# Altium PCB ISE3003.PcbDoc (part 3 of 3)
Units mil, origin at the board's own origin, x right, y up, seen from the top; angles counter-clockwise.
Board outline 3937.01 x 3937.01 mil, 2 copper layers (Top Layer, Bottom Layer), stack 62 mil thick; 230 components, 119 nets, 522 pads, 174 vias.
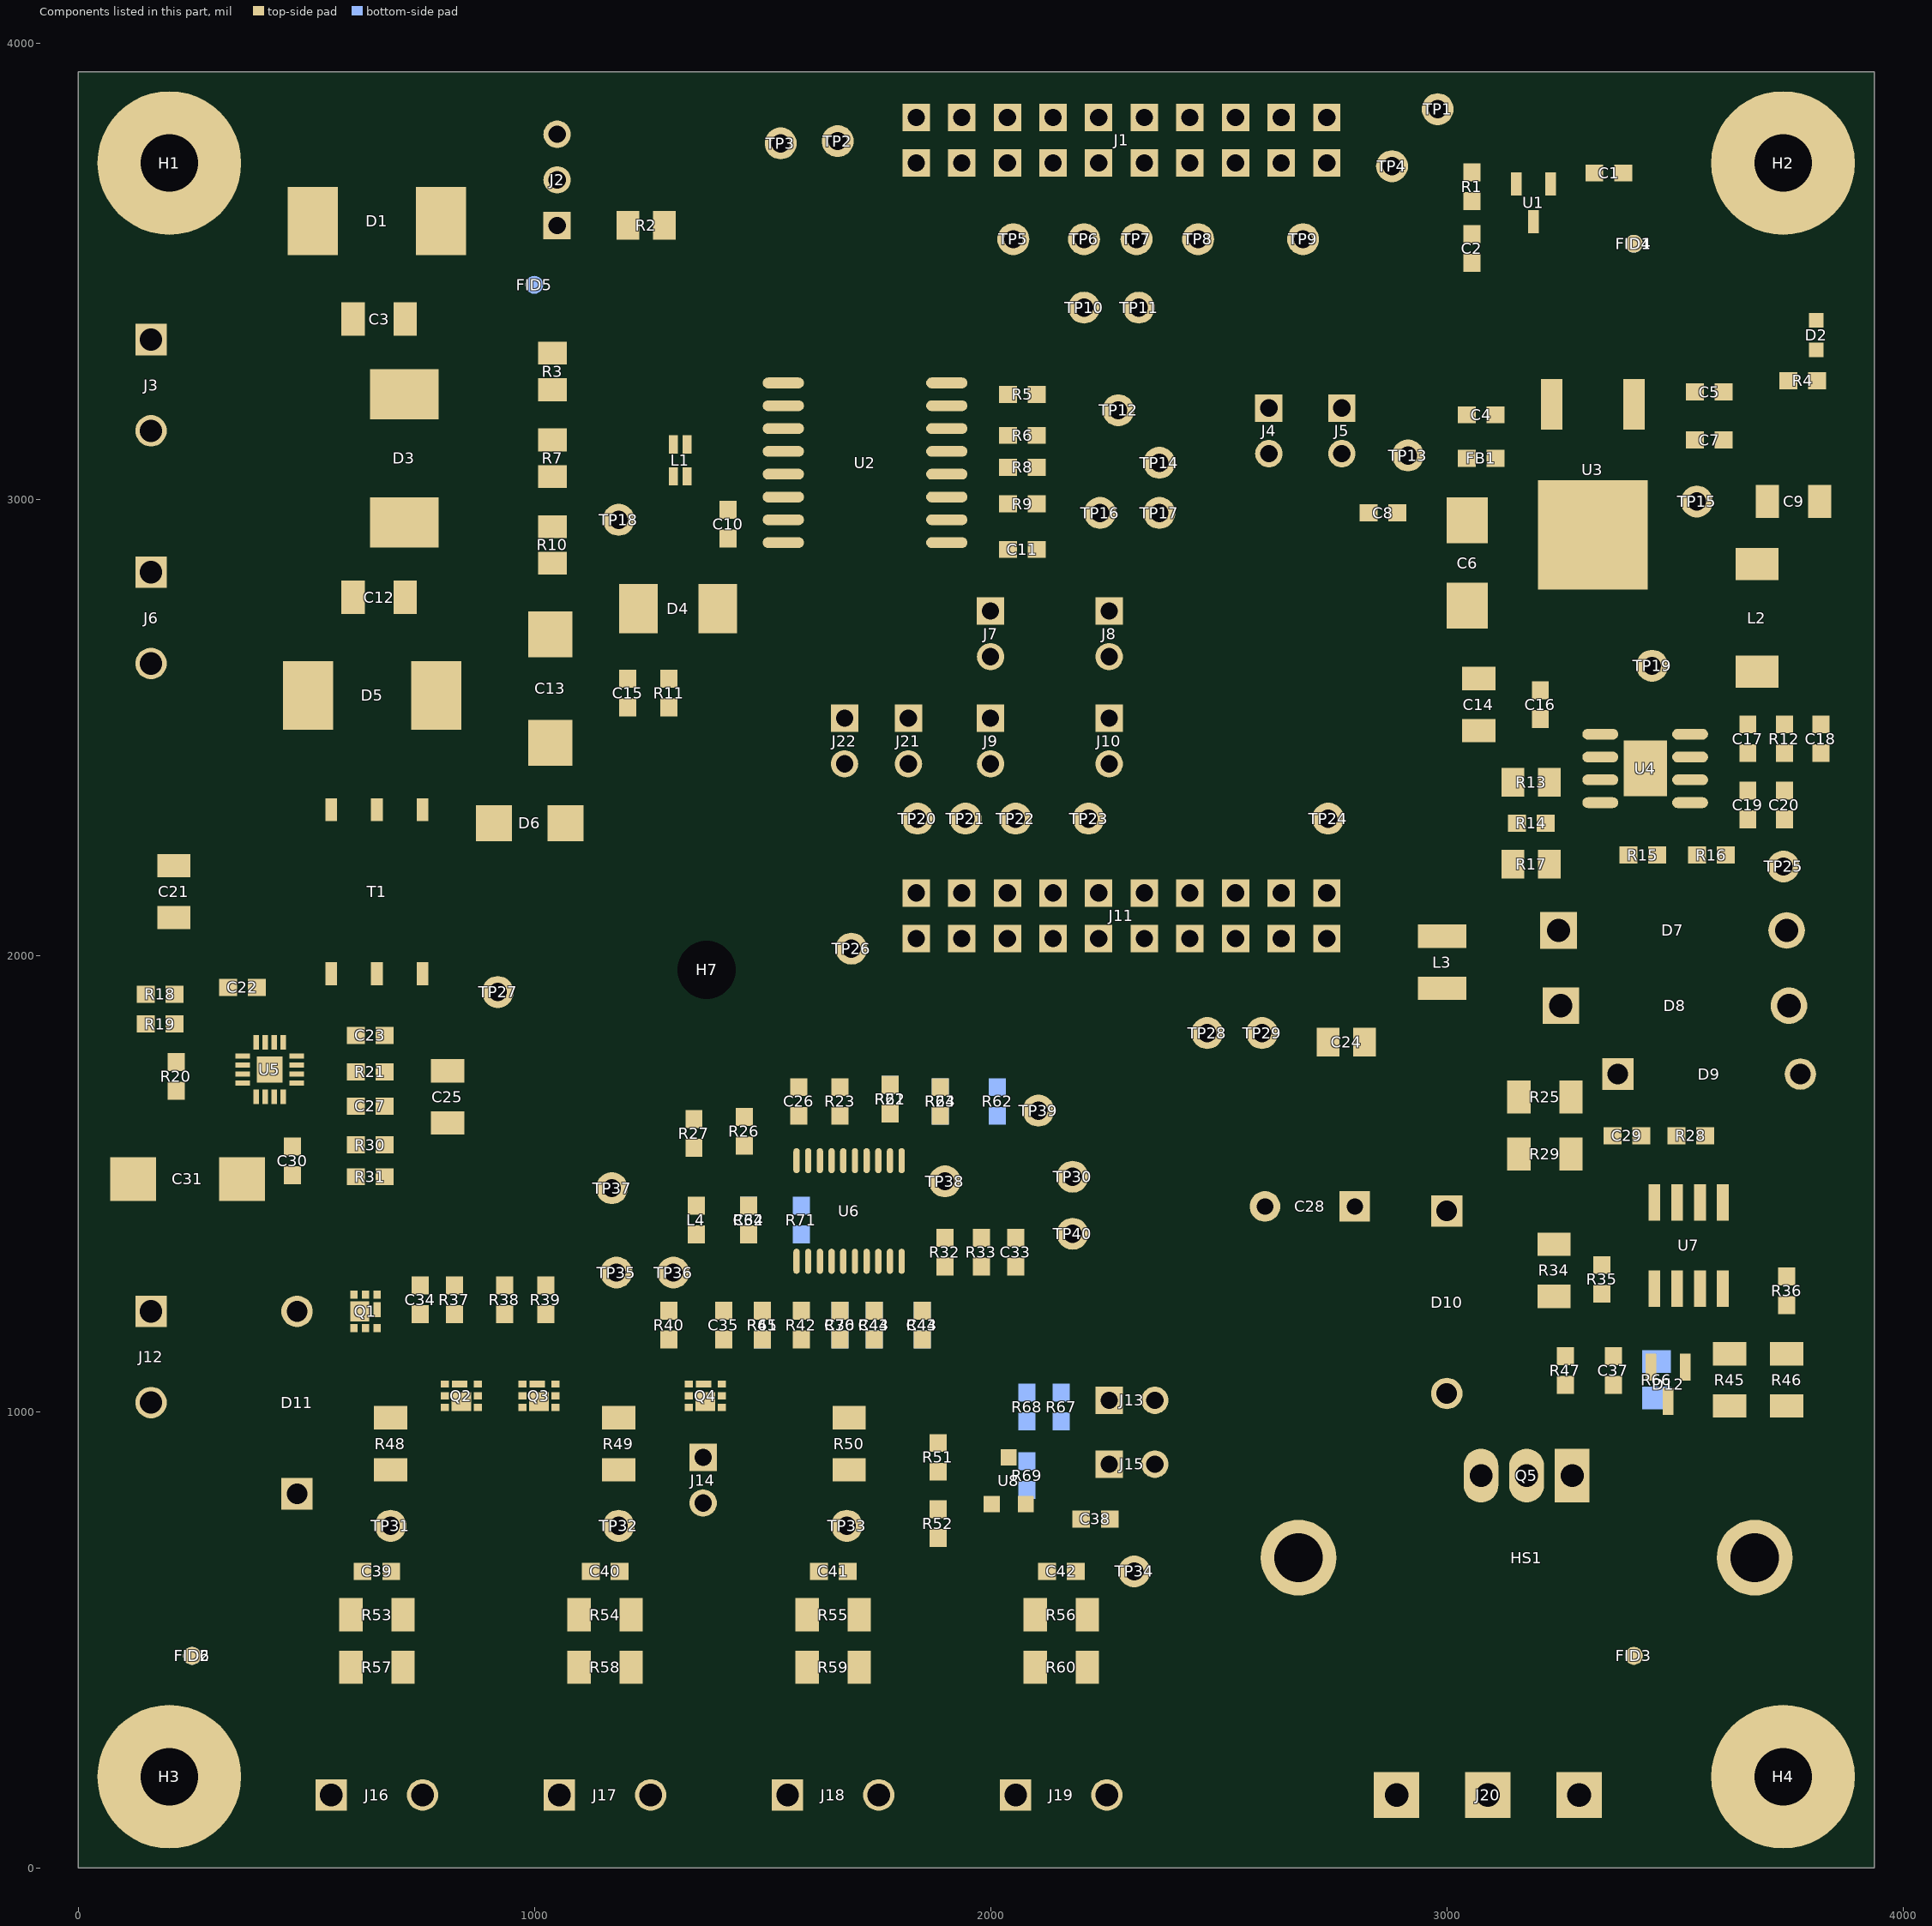
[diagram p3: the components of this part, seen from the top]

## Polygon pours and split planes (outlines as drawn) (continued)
NetQ4_1 on Top Layer "Top Layer-No Net 1" (hatched 90Degree grid 5 track 8, remove dead copper, pour order 52): 1305,1025 1310,1030 1475,1030 1485,1020 1730,1020 1740,1010 1740,965 1725,950 1465,950 1440,975 1310,975 1305,980
NetQ3_1 on Top Layer "Top Layer-No Net 1" (hatched 90Degree grid 5 track 8, remove dead copper, pour order 53): 960,955 950,965 950,1025 955,1030 1245,1030 1250,1025 1250,966.43 1240.62,955
NetC22_1 on Top Layer "Bottom Layer-No Net" (hatched 90Degree grid 5 track 8, remove dead copper, pour order 77): 425,1805 429.85,1809.55 430,1820 425,1820 425,1845 430,1850 444.95,1864.85 549.95,1864.85 568,1882.9 568,1927.95 559.95,1934.85 560,1970 560,1975 385,1975 375,1965 375,1890 360,1875 360,1810 365,1805
NetQ2_1 on Top Layer "Top Layer-No Net 1" (hatched 90Degree grid 5 track 8, remove dead copper, pour order 56): 890.18,960 900,970 900,1020 890.18,1030 762.46,1030 752.63,1020 629.82,1020 620,1010 620,970 629.82,960
NetC25_1 on Top Layer "Bottom Layer-No Net" (hatched 90Degree grid 5 track 8, remove dead copper, pour order 79): 774.57,1725 775,1830 775,1895 745,1925 745,1985 980,1985 990,1975 990,1755 960,1725
GND on Top Layer "Bottom Layer-No Net" (hatched 90Degree grid 5 track 8, remove dead copper, pour order 70): 3465,1015 3815,1015 3845,985 3845,890 3795,840 3790,840 3510,840 3500,850 3460,890 3460,945 3460,1010 3465,1015
NetC17_2 on Top Layer "Bottom Layer-No Net" (hatched 90Degree grid 5 track 8, remove dead copper, pour order 68): 3765,2485 3775,2495 3775,2660 3760,2675 3430,2675 3420,2665 3420,2610 3510,2520 3510,2485
NetC37_1 on Top Layer "Bottom Layer-No Net" (hatched 90Degree grid 5 track 8, remove dead copper, pour order 63): 3205,1100 3165,1140 3165,1255 3180,1270 3380,1270 3405,1295 3450,1295 3460,1285 3460,1200 3415,1155 3415,1110 3405,1100
NetC37_2 on Top Layer "Bottom Layer-No Net" (hatched 90Degree grid 5 track 8, remove dead copper, pour order 46): 3410,735 3435,760 3435,955 3405,985 3405,1060 3395,1070 3255,1070 3245,1060 3245,755 3265,735
NetC14_2 on Top Layer "Bottom Layer-No Net" (hatched 90Degree grid 5 track 8, remove dead copper, pour order 67): 3045,2025 3035,2015 2875,2015 2860,2035 2860,2500 2880,2520 3255,2520 3265,2510 3265,2445 3255,2435 3170,2435 3160,2425 3160,2360 3155,2355 3080,2355 3060,2335 3060,2260 3075,2245 3160,2245 3165,2240 3165,2175 3150,2160 3080,2160 3045,2125
16V_C on Top Layer "Bottom Layer-No Net" (hatched 90Degree grid 5 track 8, remove dead copper, pour order 64): 3180,1340 3285,1340 3310,1365 3310,1420 3315,1425 3460,1425 3460,1495 3385,1570 3385,1655 3415,1685 3415,1890 3375,1930 3215,1930 3205,1920 3205,1800 3245,1760 3245,1505 3165,1425 3165,1355
39V on Top Layer "Bottom Layer-No Net" (hatched 90Degree grid 5 track 8, remove dead copper, pour order 66): 2900,1410 3120,1410 3120,1465 3190,1535 3190,1720 3155,1755 3155,1935 3190,1970 3310,1970 3320,1980 3320,2100 3305,2115 3110,2115 3095,2100 3095,1985 3075,1965 2870,1965 2850,1945 2850,1910 2800,1860 2800,1750 2750,1700 2750,1390 2770,1370 2860,1370
EGND on Top Layer "Top Layer-No Net" (hatched 90Degree grid 5 track 8, remove dead copper, pour order 58): 415,3515 385,3485 385,3325 405,3305 585,3305 625,3345 625,3790 605,3810 440,3810 415,3785
NetD6_2 on Top Layer "Top Layer-No Net" (hatched 90Degree grid 5 track 8, remove dead copper, pour order 60): 750,2300 735,2315 735,2375 750,2390 890,2390 950,2330 950,2240 945,2235 870,2235 865,2240 865,2285 850,2300
C5V on Top Layer "Bottom Layer-No Net" (hatched 90Degree grid 5 track 8, remove dead copper, pour order 72): 1140,2250 1155,2270 1155,2345 1230,2420 1325,2420 1335,2430 1335,2540 1325,2550 1180,2550 1140,2510 1035,2510 1020,2495 1020,2485 1015,2480 1015,2265 1030,2250
PGND on Top Layer "Bottom Layer-No Net" (hatched 90Degree grid 5 track 8, remove dead copper, pour order 62): 925,2590 885,2630 885,2775 910,2800 1080,2800 1150,2870 1250,2870 1260,2860 1260,2600 1250,2590
PGND on Top Layer "Bottom Layer-No Net" (hatched 90Degree grid 5 track 8, remove dead copper, pour order 78): 290,2185 130,2185 110,2205 110,2340 115,2345 120,2350 235,2350 295,2350 305,2340 305,2310 305,2195 295,2185 290,2185
GND on Top Layer "Bottom Layer-No Net" (hatched 90Degree grid 5 track 8, remove dead copper, pour order 76): 85,2095 330,2095 345,2080 345,2050 345,2045 330,2030 320,2020 205,2020 90,2020 75,2035 75,2075 75,2085 85,2095
NetD10_2 on Top Layer "Bottom Layer-No Net" (hatched 90Degree grid 5 track 8, remove dead copper, pour order 51): 3135,1130 3150,1115 3150,1020 3210,960 3210,715 3275,650 3275,425 3380,320 3380,90 3350,60 3210,60 3190,80 3190,295 3140,345 3140,930 3090,980 2945,980 2925,1000 2925,1105 2950,1130
GND on Top Layer "Bottom Layer-No Net" (hatched 90Degree grid 5 track 8, remove dead copper, pour order 59): 3140,55 3025,55 3000,80 3000,920 3005,925 3100,925 3110,915 3110,805 3085,780 3085,275 3145,215 3145,60
EGND on Top Layer "Top Layer-No Net" (hatched 90Degree grid 5 track 8, remove dead copper, pour order 48): 400,2445 390,2455 390,2785 465,2860 610,2860 625,2845 625,2730 570,2675 570,2455 560,2445
12V on Top Layer "Top Layer-No Net" (hatched 90Degree grid 5 track 8, remove dead copper, pour order 43): 3730,2810 3534.33,2810 3505,2840 3505,3095 3497,3102.95 3472,3127.95 3367,3127.95 3345,3150 3345,3330 3365,3350 3550,3350 3560,3340 3560,3085 3570,3075 3740,3075 3750,3065 3750,2830
GND on Top Layer "Bottom Layer-No Net" (hatched 90Degree grid 5 track 8, remove dead copper, pour order 71): 3645,1350 3610,1385 3610,1580 3640,1610 3675,1610 3690,1625 3690,1675 3650,1715 3500,1715 3475,1740 3475,1915 3366,2024 3366,2117 3326,2157 3326,2252 3395,2321 3395,2463 3388,2470 3316,2470 3300,2486 3300,2548 3283,2565 2865,2565 2805,2505 2805,2235 2775,2205 1815,2205 1740,2130 1740,2070 1735,2065 1560,2065 1525,2100 1525,2310 1970,2755 2090,2755 2145,2810 2145,2935 2150,2940 2190,2940 2230,2900 2340,2900 2350,2910 2350,3230 2325,3255 2278,3255 2258,3275 2258,3305 2283,3330 2835,3330 2850,3315 2850,2845 2885,2810 3145,2810 3185,2850 3185,3020 3210,3045 3450,3045 3450,2790 3360,2700 3360,2605 3475,2490 3475,2327 3410,2262 3410,2160 3610,1960 3780,1960 3820,1920 3820,1370 3800,1350
NetC4_1 on Top Layer "Top Layer-No Net" (hatched 90Degree grid 5 track 8, remove dead copper, pour order 55): 3095,3085 3105,3075 3265,3075 3265,3255 3245,3275 3120,3275 3095,3250
UC3.3V on Top Layer "Top Layer-No Net" (hatched 90Degree grid 5 track 8, remove dead copper, pour order 47): 2990,2900 2965,2875 2890,2875 2880,2885 2880,3150 2895,3165 2970,3165 3000,3135 3050,3135 3055,3130 3055,3010 3065,3000 3135,3000 3145,2990 3145,2905 3140,2900
GND on Top Layer "Top Layer-No Net 1" (hatched 90Degree grid 5 track 8, remove dead copper, pour order 45): 2615,1765 2635,1745 2635,1340 2690,1285 2690,1160 2650,1120 2395,1120 2375,1140 2375,1720 2420,1765
GND on Top Layer "Bottom Layer-No Net" (hatched 90Degree grid 5 track 8, remove dead copper, pour order 69): 3800,3210 3800,3070 3815,3055 3815,2770 3820,2765 3895,2765 3900,2770 3900,3510 3885,3525 3550,3525 3505,3480 3505,3395 3515,3385 3600,3385 3615,3400 3770,3400 3795,3375 3840,3375 3850,3365 3850,3230 3840,3220 3810,3220
VREF_PH on Bottom Layer "Top Layer-No Net 1" (hatched 90Degree grid 5 track 8, remove dead copper, pour order 82): 1280,1130 1330,1180 1385,1180 1400,1165 1400,1047 1364,1011 739,1011 705,1045 705,1115 720,1130
EGND on Bottom Layer "Bottom Layer-No Net" (hatched 90Degree grid 5 track 8, remove dead copper, pour order 57): 475,2835 560,2835 580,2815 580,2521 505,2446 60,2446 35,2471 35,3425 85,3475 500,3475 550,3425 550,3235 520,3205 333,3205 305,3233 305,3385 264,3426 85,3426 70,3411 70,2705 85,2690 415,2690 445,2720 445,2805
PGND on Bottom Layer "Bottom Layer-No Net" (hatched 90Degree grid 5 track 8, remove dead copper, pour order 81): 475,2295 965,2295 1305,2630 1305,2860 1335,2890 1410,2890 1500,2980 1500,3275 1400,3375 685,3375 645,3335 645,2965 630,2950 150,2950 125,2925 125,2780 140,2765 190,2765 310,2885 650,2885 650,2430 620,2400 485,2400 435,2350 150,2350 100,2300 100,2215 130,2185 365,2185
GND on Bottom Layer "Top Layer-No Net 1" (hatched 90Degree grid 5 track 8, remove dead copper, pour order 50): 598,1335 678,1335 723,1290 723,1223 655,1155 655,1040 655,988 693,950 693,885 678,870 581,870 575,876 575,921 575,1327 583,1335
12V on Bottom Layer "Bottom Layer-No Net" (hatched 90Degree grid 5 track 8, remove dead copper, pour order 65): 3755,2760 3715,2800 3550,2800 3505,2845 3505,3015 3545,3056 3840,3056 3865,3031 3865,440 3840,415 3520,415 3375,270 440,270 325,385 325,785 305,805 140,805 100,845 100,1035 120,1055 510,1055 530,1035 530,790 415,675 415,436 506,345 2679,345 2979,645 3600,645 3660,705 3660,1060 3630,1090 3630,1620 3620,1630 3520,1630 3510,1640 3510,1675 3550,1715 3550,2135 3755,2340
GND on Bottom Layer "Bottom Layer-No Net" (hatched 90Degree grid 5 track 8, remove dead copper, pour order 61): 3850,3900 3900,3850 3900,3165 3835,3100 3480,3100 3465,3085 3465,2710 3485,2690 3665,2690 3683,2670 3713,2640 3715,2345 3520,2150 3520,1770 3600,1690 3600,815 3465,680 2920,680 2650,410 590,410 460,540 460,680 575,795 575,925 615,965 1405,965 1430,990 1430,1185 1335,1280 1305,1280 1295,1270 1295,1195 1275,1175 665,1175 560,1280 110,1280 50,1340 50,2080 80,2110 350,2110 470,1990 470,1860 500,1830 969,1830 1020,1881 1020,1970 1040,1990 1210,1990 1990,2770 1990,3240 1950,3280 1950,3540 1780,3710 1780,3880 1800,3900

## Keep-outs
Keep-Out Layer:
  lines w10: -5,3969.53 -5,-5 3970.75,-5 3970.75,3969.52 ; 0,3969.53 3969.53,3969.53
  text ".Layer_Name" at 577,-858.49 h60

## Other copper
Top Layer:
  pour cut-out: 2390.95,2915 2425,2949.05 2425,3113 2393,3145 2305,3145 2280,3120 2280,2915
  pour cut-out: 1925,2723 1983,2665 2055,2665 2055,2790 2045,2800 1935,2800 1925,2790
  pour cut-out: 2716,3050 2729,3037 2804,3037 2823,3056 2823,3240 2809,3254 2726,3254 2716,3244
  pour cut-out: 2561,3055 2574,3042 2649,3042 2668,3061 2668,3245 2654,3259 2571,3259 2561,3249
  pour cut-out: 1786.15,2322.48 1823.67,2360 2083,2360 2115,2328 2115,2255 1786.15,2255
  pour cut-out: 1880,2260 1880,2563 1823,2620 1700,2620 1645,2565 1645,2260
  text ".Layer_Name" at 577,-858.49 h60
Bottom Layer:
  pour cut-out: 2418,3522 2516,3522 2516,3578 2514,3580 2428,3580 2415,3567 2415,3525 2417,3523 2418,3523
  pour cut-out: 3618,1627 3610,1635 3575,1635 3566.5,1626.5 3566.5,1443 3618,1443
  pour cut-out: 3432.5,1333.5 3545,1221 3545,1180 3448,1180 3325,1303 3325,1333.5
  pour cut-out: 3405,1231 3403,1229 3403,980 3523,980 3563,1020 3563,1183 3541,1205 3458,1205 3433,1230 3406,1230
  pour cut-out: 3550,1685 3550,1755 3555,1760 3610,1705 3610,1686 3581,1686 3575,1680 3555,1680
  pour cut-out: 3040,3930 3040,3790 3025,3775 2905,3775 2875,3805 2875,3920 2885,3930
  pour cut-out: 2755,3075 2800,3030 2810,3030 2855,3075 2855,3245 2820,3280 2794,3280 2753,3239 2753,3080
  pour cut-out: 2897.29,3705 2937.29,3665 2960,3665 2965,3670 2965,3770 3018,3823 3018,3907 2995,3930 2775,3930 2725,3880 2725,3735 2755,3705
  pour cut-out: 2695,3675 2778,3675 2810,3707 2810,3786 2800,3796 2736,3796 2715,3775 2695,3775
  pour cut-out: 2659,3416 2635,3440 2540,3440 2535,3435 2535,3375 2549,3361 2586,3361 2586,3274 2561,3249 2561,3132 2561.01,3101 2561.16,3096 2561.83,3091 2660.14,3090
  pour cut-out: 2170,3350 2175,3345 2219,3345 2251.92,3377.92 2290.08,3377.92 2303,3365 2357.87,3365 2410,3417.13 2410,3430 2390,3450 2180,3450 2170,3440
  pour cut-out: 2125,3115 2180,3115 2180,3090 2125,3090
  pour cut-out: 2371,3391 2245.73,3391 2125,3511.73 2125,3640 2150,3665 2405,3665 2435,3635 2435,3455
  pour cut-out: 2385,3050 2385,3100 2285,3200 2200,3200 2200,3060 2225,3035 2370,3035
  pour cut-out: 2405,2921 2219,2921 2200,2940 2200,3060 2385,3060 2385,2940 2395,2930 2405,2930
  pour cut-out: 1915,2200 1885,2230 1885,2745 1949.5,2809.5 2291.5,2809.5 2323,2778 2323,2213 2310,2200
  pour cut-out: 1715,1415 1715,1385 1690,1360 1690,1355 1655,1355 1645,1365 1645,1410 1650,1415
  pour cut-out: 1535,1600 1535,1675 1650,1790 1885,1790 1885,1695 1919.89,1695 1933,1681.89 1933,1600
  pour cut-out: 1495,1645 1495,1700 1505,1710 1510,1705 1550,1705 1550,1695 1560,1685 1555,1680 1555,1650 1535,1650 1530,1645
  pour cut-out: 1663,1614.82 1662.82,1615 1595,1615 1595,1690 1610,1705 1665,1705 1680,1690 1680,1616.82 1678,1614.82
  pour cut-out: 1808,1614.82 1660.18,1614.82 1645,1630 1645,1730 1690,1775 1880,1775 1898,1757 1898,1633 1880,1615 1808.18,1615
  pour cut-out: 1959.82,1260.18 1965,1255 1965,1190 1957.81,1182.81 1710.19,1182.81 1698,1195 1698,1250.88 1707.3,1260.18
  pour cut-out: 2170,1075 2170,1085 2378,1085 2413,1050 2413,975 2393,955 2180,955 2160,975 2160,1065
  pour cut-out: 3065,1335 3065,1525 2920,1525 2920,1366 2951,1335
  pour cut-out: 1480,670 1480,705 1475,710 1445,680 1445,670 1455,670 1460,665 1475,665
  pour cut-out: 1600,740 1715,740 1715,720 1735,700 1755,700 1765,710 1765,765 1785,785 1785,845 1755,875 1700,875 1670,905 1660,905 1525,770 1525,750 1525.23,750 1545.23,730 1595,730 1600,735
  pour cut-out: 1315,1250 1305,1255 1303,1278 1398,1370 1480,1370 1480,1305 1475,1300 1385,1300 1335,1250
  pour cut-out: 1580,918 1580,910 1550,880 1490,880 1475,895 1475,947 1493,965 1533,965
  pour cut-out: 1321,769 1325,765 1410,765 1530,885 1530,970.77 1509.77,991 1345,991 1321,967
  pour cut-out: 1410,770 1394,786 1201,786 1185,770 1185,705 1195,695 1405,695 1410,700
  pour cut-out: 1530,1205 1537.7,1212.7 1537.7,1307.3 1530,1315 1465,1315 1462.3,1312.3 1462.3,1206 1463.3,1205
  pour cut-out: 2228,836 2180.24,836 2099.24,755 2041,755 2041,1101 2063,1123 2136,1123 2148,1111 2148,928 2163,913 2228,913
  pour cut-out: 2785,2191 2800,2176 2800,2016 2764,1980 1798,1980 1770,2008 1770,2171 1790,2191
  pour cut-out: 2785,3891 2800,3876 2800,3716 2764,3680 1798,3680 1770,3708 1770,3871 1790,3891
  pour cut-out: 1420,2870 1335,2870 1325,2880 1325,2942 1338,2955 1413,2955 1420,2948 1420,2895 1425,2890 1425,2875
  pour cut-out: 1455,2880 1410,2925 1400,2925 1396.46,2921.46 1396.46,2868.54 1405,2860 1450,2860 1455,2865
  pour cut-out: 3328,773 3343,788 3343,938 3333,948 3152,948 3118.87,914.87 3118.87,784.13 3130,773
  pour cut-out: 1605.06,1875 1605.06,1970 1635.06,2000 1650,2000 1690,1960 1690,1900 1665,1875
  pour cut-out: 1575,2380 1620,2335 1670,2335 1690,2355 1690,2445 1670,2465 1590,2465 1575,2450
  pour cut-out: 2126,1607 2024,1607 2024,1681 2044,1701 2150,1701 2153.78,1697.22 2153.78,1634.78
  pour cut-out: 1344,1461 1306,1499 1281,1474 1216,1474 1158,1416 1158,1345 1175,1345 1209,1311 1265,1367 1265,1375 1333,1375 1344,1386
  pour cut-out: 1225,1630 1175,1630 1165,1640 1210,1685 1260,1685 1270,1675 1260,1665 1260,1655 1250,1655
  text ".Layer_Name" at 577,-858.49 h60

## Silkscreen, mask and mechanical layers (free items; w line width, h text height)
Top Overlay:
  circle w15: c1380,3050 r6
  circle w8: c751,1861 r38
  circle w8: c1066,1918 r38
  lines w6: 480.57,1658 328,1658 328,1842 512,1842 512,1690 ; 712,1820 712,1866 566,1866 566,1464 714,1464 714,1600 ; 713,1669 713,1755 ; 1255,1380 1275,1360 ; 1903,2420 1903,2349 1916,2336 ; 2025,1110 1885,1110 ; 2790,90 3390,90 ; 2845,428 2806,428 2806,485 2513,485 2513,871 2807,871 2807,928 2846,928 ; 2847,429 2847,649 3505,649 3505,428 ; 2847,930 2847,712 3504,712 3505,712 3505,928 3544,928 3544,871 3838,871 3838,485 3545,485 3545,428 3506,428 ; 2989,3 2989,90 ; 3190,3 3190,90 ; 3770,2407 3789,2388 3803,2388 ; 3842,2241 3770,2241 ; 1885,1110 1895,1120 1895,1100 1885,1110 ; 3770,2241 3770,2240 3775,2235 3775,2246 3770,2241 ; 1017,1566 1163,1566 1163,1879 1017,1879 1017,1566 ; 1275,3015 1275,3155 1365,3155 1365,3015 1275,3015 ; 1921,1127 1929,1119 1929,1135 1921,1127 ; 1950,765 2130,765 2130,935 1950,935 1950,765 ; 2790,3 3390,3 3390,357 2790,357 2790,3 ; 3415,1215 3645,1215 3645,1514 3415,1514 3415,1215
  text "1" at 2808,3848 h40
  text "19" at 1703,3842 h40
  text "2" at 2718,3632 h40
  text "ISE3003" at 2555,3375 h40
  text "19" at 1800,2200 h40
  text "1" at 2807,2125 h40
  text "2" at 2810,2018 h40
  text "20" at 1792,1925 h40
  text "A" at 1046,1898 h50
  text "A" at 731,1841 h50
  text ".Layer_Name" at 577,-858.49 h40
Bottom Overlay:
  text ".Layer_Name" at 577,-858.49 h40
Top Paste:
  text ".Layer_Name" at 577,-858.49 h60
Bottom Paste:
  text ".Layer_Name" at 577,-858.49 h60
Top Solder:
  text ".Layer_Name" at 577,-858.49 h60
  text ".Layer_Name" at 577,-858.49 h60
Bottom Solder:
  text ".Layer_Name" at 577,-858.49 h60
Drill Guide:
  text ".Layer_Name" at 577,-858.49 h60
M1 Board Outline:
  the board outline again, w10
  text ".Layer_Name" at 577,-856 h60
M2 Board Dimensions:
  rectangle: -0.5,-285.5 124.5,-160.5
  rectangle: 124.5,-410.5 499.5,-285.5
  lines w7: -0.5,-285.5 999.5,-285.5 ; 124.5,-410.5 124.5,-160.5 ; 249.5,-410.5 249.5,-160.5 ; 499.5,-410.5 499.5,-160.5 ; 749.5,-410.5 749.5,-160.5 ; -0.5,-410.5 999.5,-410.5 999.5,-160.5 -0.5,-160.5 -0.5,-410.5
  lines w10: -0.5,-475.5 -0.5,-455.5 ; 59.5,-485.5 -0.5,-465.5 ; 59.5,-445.5 -0.5,-465.5 ; 223.58,-465.5 -0.5,-465.5 ; 775.42,-465.5 999.5,-465.5 ; 939.5,-485.5 999.5,-465.5 ; 939.5,-445.5 999.5,-465.5 ; 999.5,-475.5 999.5,-455.5
  text "1000 (mil)" at 233.58,-501.49 h60
  text ".Layer_Name" at 577,-858.49 h60
M3 3D STEP Top:
  text ".Layer_Name" at 577,-858.49 h60
M4 3D STEP Bottom:
  text ".Layer_Name" at 577,-858.49 h60
M5 Assembly Top:
  circle w15: c3259.79,3691.34 r6
  circle w15: c557,1962 r6
  lines w6: 3130.94,3650 3130.94,3622.44 3162.44,3622.44 ; 3217.56,3622.44 3249.06,3622.44 3249.06,3650 ; 3784.96,3466.79 3834.96,3466.79 ; 3794.25,3348.58 3794.25,3371.42 ; 3809.96,3416.79 3809.96,3441.79 ; 3809.96,3491.79 3809.96,3466.79 ; 3825.75,3348.58 3825.75,3371.42 ; 3809.96,3466.79 3834.96,3441.79 3784.96,3441.79 3809.96,3466.79 ; 505,1920.63 805,1920.63 805,2361.57 505,2361.57 505,1920.63
  lines w10: -292,-930.17 6308,-930.17 ; -292,-726.83 6310,-726.83 ; -292,-523.5 -292,-1133.5 3713,-1133.5 6310,-1133.5 6310,-523.5 -291.5,-523.5 -291.5,-1133.5 1284,-1133.5 ; 2173,-1133.5 2173,-523.5 ; 3440,-726.83 3440,-523.5 ; 4280,-726.83 4280,-523.5 ; 4902,-1140 4902,-937.17
  text "D2" at 3877,3338 h36 r90
  text "T1" at 620,2129 h40
  text "COMPONENTS MARKED 'DNP' SHOULD NOT BE POPULATED." at 1153.5,-318.5 h60
  text "ASSEMBLY VARIANT:" at 1153,-434 h60
  text ".VariantName" at 2189,-434 h60
  text "PCB VIEWED FROM TOP SIDE" at -228.5,-655.67 h60
  text "BOARD #:" at 2248,-655.67 h60
  text ".PRJ_Number" at 2793.5,-655.67 h60
  text "REV:" at 3638,-655.67 h60
  text ".PCB_Rev" at 3929.5,-655.67 h60
  text "SVN REV:" at 4476,-655.67 h60
  text ".VersionControl_RevNumber" at 4982,-655.67 h60
  text "IGNORE ->" at -228.5,-858.49 h60
  text "PLOT NAME =" at -228.5,-1064.34 h60
  text ".plot_File_Name" at 577,-1064.34 h60
  text "GENERATED    :" at 2250,-1064.34 h60
  text ".Print_Date" at 3119.5,-1064.34 h60
  text ".Print_Time" at 3848.5,-1064.34 h60
  text "TEXAS INSTRUMENTS" at 5113,-1064.34 h60
M6 Assembly Bottom:
  lines w10: -292.5,-727.33 6309.5,-727.33 ; -290.5,-930.67 6309.5,-930.67 ; 1115.5,-1140.5 1115.5,-937.67 ; 1737.5,-727.33 1737.5,-524 ; 2577.5,-727.33 2577.5,-524 ; 3844.5,-1134 3844.5,-524 ; 4733.5,-1134 6309,-1134 6309,-524 -292.5,-524 -292.5,-1134 2304.5,-1134 6309.5,-1134 6309.5,-524
  text "COMPONENTS MARKED 'DNP' SHOULD NOT BE POPULATED." at 6102,-318 h60
  text ".VariantName" at 5058,-434 h60
  text "ASSEMBLY VARIANT:" at 6097,-434 h60
  text ".VersionControl_RevNumber" at 1035.5,-656.17 h60
  text "SVN REV:" at 1541.5,-656.17 h60
  text ".PCB_Rev" at 2088,-656.17 h60
  text "REV:" at 2379.5,-656.17 h60
  text ".PRJ_Number" at 3224,-656.17 h60
  text "BOARD #:" at 3769.5,-656.17 h60
  text "PCB VIEWED FROM BOTTOM SIDE" at 6246,-656.17 h60
  text "IGNORE ->" at 2547.85,-858.49 h60
  text "TEXAS INSTRUMENTS" at 904.5,-1064.84 h60
  text ".Print_Time" at 2169,-1064.84 h60
  text ".Print_Date" at 2898,-1064.84 h60
  text "GENERATED    :" at 3767.5,-1064.84 h60
  text ".plot_File_Name" at 5440.5,-1064.84 h60
  text "PLOT NAME =" at 6246,-1064.84 h60
M7 LPKF Text Top:
  lines w10: 1337.01,1937.01 1337.01,3937.01 3937.01,3937.01 3937.01,1937.01 1337.01,1937.01
M9 Title Sheet:
  drawing of 57 lines, arcs and shapes, not listed
  text "1" at 739.84,8036.5 h70
  text "2" at 3235.5,8036.5 h70
  text "3" at 5724.84,8036.5 h70
  text "4" at 8231.51,8036.5 h70
  text "5" at 10730.5,8036.5 h70
  text "6" at 13235.5,8036.5 h70
  text "A" at -416.5,6893.5 h70
  text "A" at 14383.5,6893.5 h70
  text "B" at -416.5,4513.5 h70
  text "B" at 14383.5,4513.5 h70
  text "C" at -416.5,2138.5 h70
  text "C" at 14383.5,2138.5 h70
  text "PROJECT TITLE:" at 11343.5,277.5 h45
  text ".PRJ_Title" at 11393.5,144.17 h70
  text "DESIGNED FOR:" at 11343.5,-23.5 h45
  text ".PRJ_Customer" at 11393.5,-163.5 h70
  text "D" at -416.5,-231.5 h70
  text "D" at 14383.5,-231.5 h70
  text "FILE NAME:" at 11343.5,-323.5 h45
  text "ISE3003" at 11378,-445.67 h60
  text "Texas Instruments (TI) and/or its licensors do not warrant the accuracy or completeness of this specification" at 6374,-605.34 h45
  text "ENGINEER:" at 11343.5,-613.5 h45
  text "LAYOUT BY:" at 12848.5,-613.5 h45
  text "or any information contained therein. TI and/or its licensors do not warrant that this design will meet" at 6329.01,-718 h45
  text "the specifications, will be suitable for your application or fit for any particular purpose, or will operate in" at 6329.01,-830.67 h45
  text "ALTIUM DESIGNER VERSION:" at 12848.5,-923.5 h45
  text "an implementation. TI and/or its licensors do not warrant that the design is production worthy. You should" at 6329.01,-943.33 h45
  text "completely validate and test your design implementation to confirm the system functionality for your application." at 6374,-1056 h45
  text ".print_Scale" at 11393.5,-1056.83 h70
  text ".Application_BuildNumber" at 12899,-1056.83 h70
  text "1" at 739.84,-1263.5 h70
  text "2" at 3235.5,-1263.5 h70
  text "3" at 5724.84,-1263.5 h70
  text "4" at 8231.51,-1263.5 h70
  text "5" at 10730.5,-1263.5 h70
  text "6" at 13235.5,-1263.5 h70
M10 Fab Notes:
  drawing of 212 lines, arcs and shapes, not listed
  text "DESIGN INFORMATION" at 12381.02,6810 h60
  text "(REFER ALSO ARRAY/PANEL PROFILING INFORMATION)" at 12019.46,6648.29 h60
  text "BOARD SIZE" at 11333.46,6644 h60
  text "3937MIL" at 11795.78,6516.18 h60
  text "X" at 12301.46,6516.18 h60
  text "3937MIL" at 12532.78,6516.18 h60
  text "Number of Layers :" at 11736.46,6319 h60
  text "2" at 12831.27,6309 h60
  text "MIN. TRACK WIDTH:" at 11736.46,6180 h60
  text "10" at 12832.7,6180 h60
  text "MIL" at 12987.46,6180 h60
  text "MIN. CLEARANCE:" at 11736.46,6048 h60
  text "MIL" at 12987.46,6048 h60
  text "5.7" at 12790.46,6042.61 h60
  text "MIN. VIA PAD SIZE:" at 11736.46,5916 h60
  text "26" at 12802.71,5916 h60
  text "MIL" at 12987.46,5916 h60
  text "0.177 mm (7MIL)" at 12431.46,5774.29 h60
  text "MINIMUM ANNULAR RING" at 11407.23,5770 h60
  text "EXTERNAL" at 13176.5,5767.69 h60
  text "PER" at 11607.23,5652 h60
  text "IPC-D-275 CLASS 2 LEVEL C" at 11827.23,5652 h60
  text "MIL, HOLES" at 13315.46,5539.71 h60
  text "+/-" at 12923,5539 h60
  text "+/-" at 13777,5539 h60
  text "REGISTRATION TOLERANCES:" at 11407.23,5534 h60
  text "METAL" at 12607,5534 h60
  text "5" at 13183.2,5534 h60
  text "3" at 14016.2,5534 h60
  text "MIL" at 14132.46,5534 h60
  text "MATERIAL:" at 11332.46,5324.54 h60
  text "FR-4 High Tg" at 12318.9,5184.21 h60
  text "FR-408" at 11753.46,5175.64 h60
  text "X" at 12165.46,5175.64 h60
  text "OTHER" at 13241.46,5175.64 h60
  text "62 MIL (1.6mm) +/-10%" at 12073.56,5012.92 h60
  text "THICKNESS:" at 11407.23,5008.64 h60
  text "X" at 11945.4,5008.64 h60
  text "OTHER" at 13358.46,5008.64 h60
  text "TOLERANCE:" at 11407.23,4850.64 h60
  text "X" at 12246.53,4850.64 h60
  text "ANSI IPC-6012 TYPE 3 CLASS 2" at 12433.48,4850.64 h60
  text "OTHER +/-" at 12433.46,4694.64 h60
  text "BOW & TWIST:" at 11407.23,4537.64 h60
  text "X" at 12246.53,4537.64 h60
  text "ANSI IPC-6012 TYPE 3 CLASS 2" at 12433.48,4537.64 h60
  text "OTHER +/-" at 12433.46,4379.13 h60
  text "COPPER THICKNESS (FINISHED):" at 11332.46,4243.64 h60
  text "1.4MIL (1oz)" at 12212.46,4090.92 h60
  text "2MIL (1.4oz)" at 12979.46,4090.92 h60
  text "2.8MIL (2oz)" at 13706.46,4090.92 h60
  text "OUTER:" at 11689.46,4086.64 h60
  text "X" at 12084,4086 h60
  text "1.4MIL (1oz)" at 12212.46,3933.92 h60
  text "2.8MIL (2oz)" at 12979.46,3933.92 h60
  text "N/A" at 13706,3934.29 h60
  text "INNER SIGNAL:" at 11400.38,3929.64 h60
  text "DRILLING:" at 11332.46,3790.64 h60
  text "REFERENCE:" at 11407.23,3673.64 h60
  text "X" at 12055.46,3673.64 h60
  text "AS SHOWN" at 12242.46,3673.64 h60
  text "X" at 12956.46,3673.64 h60
  text "NC_DRILL FILES" at 13093.46,3673.64 h60
  text "PTH MIN COPPER THICKNESS:" at 11407.23,3515.64 h60
  text "X" at 12757.46,3515.64 h60
  text "1MIL" at 12894.46,3515.64 h60
  text "OTHER" at 13391.46,3515.64 h60
  text "BOARD FINISH:" at 11332.46,3356.64 h60
  text "SILKSCREEN:" at 11487.68,3238.64 h60
  text "X" at 12436.46,3238.64 h60
  text "TOP" at 12562.46,3238.64 h60
  text "X" at 12946.46,3238.64 h60
  text "BOTTOM" at 13073.46,3238.64 h60
  text "SILKSCREEN COLOR:" at 11487.68,3071.64 h60
  text "X" at 12435.42,3071.64 h60
  text "WHITE" at 12562.46,3071.64 h60
  text "OTHER" at 13073.46,3071.64 h60
  text "SOLDER RESIST COLOR:" at 11487.68,2901.64 h60
  text "X" at 12055.42,2742.44 h60
  text "GREEN" at 12182.46,2742.44 h60
  text "BLUE" at 12773.46,2742.44 h60
  text "OTHER" at 13311.46,2742.44 h60
  text "IMMERSION GOLD (ENIG)" at 12393.46,2553.92 h60
  text "ENEPIG" at 13731,2550.64 h60
  text "SURFACE FINISH:" at 11332.46,2549.64 h60
  text "X" at 12206.51,2549.64 h60
  text "IMM. TIN/SILVER OR EQUIV" at 11662,2392.64 h60
  text "OTHER" at 13093.46,2392.64 h60
  text "ARRAY/PANEL:" at 11332.46,2213.64 h60
  text "CUT AND TRIM PER MECH LAYER 1" at 12393.46,2209.35 h60
  text "N.C. ROUTE" at 12393.46,2057.64 h60
  text "X" at 13072.46,2057.64 h60
  text "V. SCORE" at 13259.46,2057.64 h60
  text "CERTIFICATION:" at 11332.46,1920.64 h60
  text "MATERIALS AND WORKMANSHIP FOR ALL PCBS" at 12057.46,1920.64 h60
  text "TO MEET OR EXCEED THE REQUIREMENTS OF:" at 12057.46,1822.64 h60
  text "X" at 11683.96,1686.13 h60
  text "ANSI IPC-A-600F CLASS ->" at 11822.96,1686.13 h60
  text "X" at 13462.02,1686.13 h60
  text "2" at 13580.96,1686.14 h60
  text "1" at 13265.96,1684.64 h60
  text "3" at 13934.96,1684.64 h60
  text "X" at 11686.02,1526.64 h60
  text "UL 94V-0" at 11822.96,1526.64 h60
  text "X" at 12498.02,1526.64 h60
  text "RoHS" at 12634.96,1526.64 h60
  text "OTHER" at 13279.36,1526.64 h60
  text "PER ORDER" at 13676.42,1526.64 h60
  text "ADDITIONAL REQUIREMENTS:" at 11332.46,1385.64 h60
  text "MICROSECTION:" at 11407.23,1270.64 h60
  text "YES" at 12312.96,1270.64 h60
  text "REQUIRED" at 13174.46,1114.49 h60
  text "BARE BOARD ELEC. TEST:" at 11407.23,1111.64 h60
  text "NONE" at 12712.96,1111.64 h60
  text "X" at 13047.46,1111.64 h60
  text "PER ORDER" at 13766.46,1111.64 h60
  text "MANUFACTURER'S UL:" at 11407.23,954.64 h60
  text "RAIL" at 12572.96,950.35 h60
  text "METAL" at 13064.77,950.35 h60
  text "X" at 13440,950 h60
  text "SILK" at 13576.46,950.35 h60
M11 Gerber Information:
  lines w10: -292,-930.17 6308,-930.17 ; -292,-726.83 6310,-726.83 ; -292,-523.5 -292,-1133.5 3713,-1133.5 6310,-1133.5 6310,-523.5 -291.5,-523.5 -291.5,-1133.5 1284,-1133.5 ; 2173,-1133.5 2173,-523.5 ; 3440,-726.83 3440,-523.5 ; 4280,-726.83 4280,-523.5 ; 4902,-1140 4902,-937.17
  text "ALL ARTWORK VIEWED FROM TOP SIDE" at -228.5,-655.67 h60
  text "BOARD #:" at 2248,-655.67 h60
  text "TIDA-00130" at 2793.5,-655.67 h60
  text "REV:" at 3638,-655.67 h60
  text ".PCB_Rev" at 3929.5,-655.67 h60
  text "SVN REV:" at 4476,-655.67 h60
  text ".VersionControl_RevNumber" at 4982,-655.67 h60
  text "TIDA-00130 PGA BASED MCCB-ETU" at 2378,-855.67 h60
  text "LAYER NAME =" at -228.5,-858.49 h60
  text "PLOT NAME =" at -228.5,-1064.34 h60
  text ".plot_File_Name" at 577,-1064.34 h60
  text "GENERATED    :" at 2250,-1064.34 h60
  text ".Print_Date" at 3119.5,-1064.34 h60
  text ".Print_Time" at 3848.5,-1064.34 h60
  text "TEXAS INSTRUMENTS" at 5113,-1064.34 h60
M12 Stackup:
  lines w6: 11360,7460 13910,7460 ; 11360,7564.4 13910,7564.4 ; 11300,6975 ccw(c11334,6975) 11334,6941 13936,6941 ccw(c13936,6975) 13970,6975 13970,7681 ccw(c13936,7681) 13936,7715 11334,7715 ccw(c11334,7681) 11300,7681 11300,6975
  text "The Stackup Legend below this is static." at 11605.5,7874.5 h60
  text "If you change the stackup, update the Legend." at 11615.5,7784.5 h60
  text "Layer Stack Up Detail for: Ref_Design.PcbDoc" at 11360,7597.1 h57
  text "Layer" at 11360,7525.4 h24
  text "Gerber" at 12255.81,7525.4 h24
  text "Copper" at 12819.33,7525.4 h24
  text "Dielectric" at 13422.04,7525.4 h24
  text "Name" at 11360,7477.4 h24
  text "Document" at 12255.81,7477.4 h24
  text "Thickness" at 12819.33,7477.4 h24
  text "Material" at 13422.04,7477.4 h24
  text "Top Solder Mask" at 11360,7384.44 h34
  text "(.GTS)" at 12255.81,7384.44 h34
  text "Solder Resist" at 13422.04,7384.44 h34
  text "Top Layer" at 11360,7287.69 h34
  text "(.GTL)" at 12255.81,7287.69 h34
  text "1.4mil" at 12819.33,7287.69 h34
  text "FR-4" at 13422.04,7239.31 h34
  text "Bottom Layer" at 11360,7190.94 h34
  text "(.GBL)" at 12255.81,7190.94 h34
  text "1.4mil" at 12819.33,7190.94 h34
  text "Bottom Solder Mask" at 11360,7094.19 h34
  text "(.GBS)" at 12255.81,7094.19 h34
  text "Solder Resist" at 13422.04,7094.19 h34
  text ".Layer_Name" at 577,-858.49 h60
M13 Component Bodies Top:
  text ".Layer_Name" at 577,-858.49 h60
M14 Component Bodies Bottom:
  text ".Layer_Name" at 577,-858.49 h60
M15 Courtyards Top:
  text ".Layer_Name" at 577,-858.49 h60
M16 Courtyards Bottom:
  text ".Layer_Name" at 577,-858.49 h60
Drill Drawing:
  text ".legend" at 4328.68,813.56 h60
  text "Drill Table" at 4354.19,628.11 h60
  text "FOR PTH +/-3MILS" at 5420.81,385.39 h60
  text "DRILL TOLERANCES:" at 4377.47,379.19 h60
  text "FOR NPTH +/-2MILS" at 5423.2,241.61 h60
  text ".Layer_Name" at 577,-858.49 h60

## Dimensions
0,3937.01 to 3937.01,3937.01 on M2 Board Dimensions
0,0 to 0,3937.01 on M2 Board Dimensions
